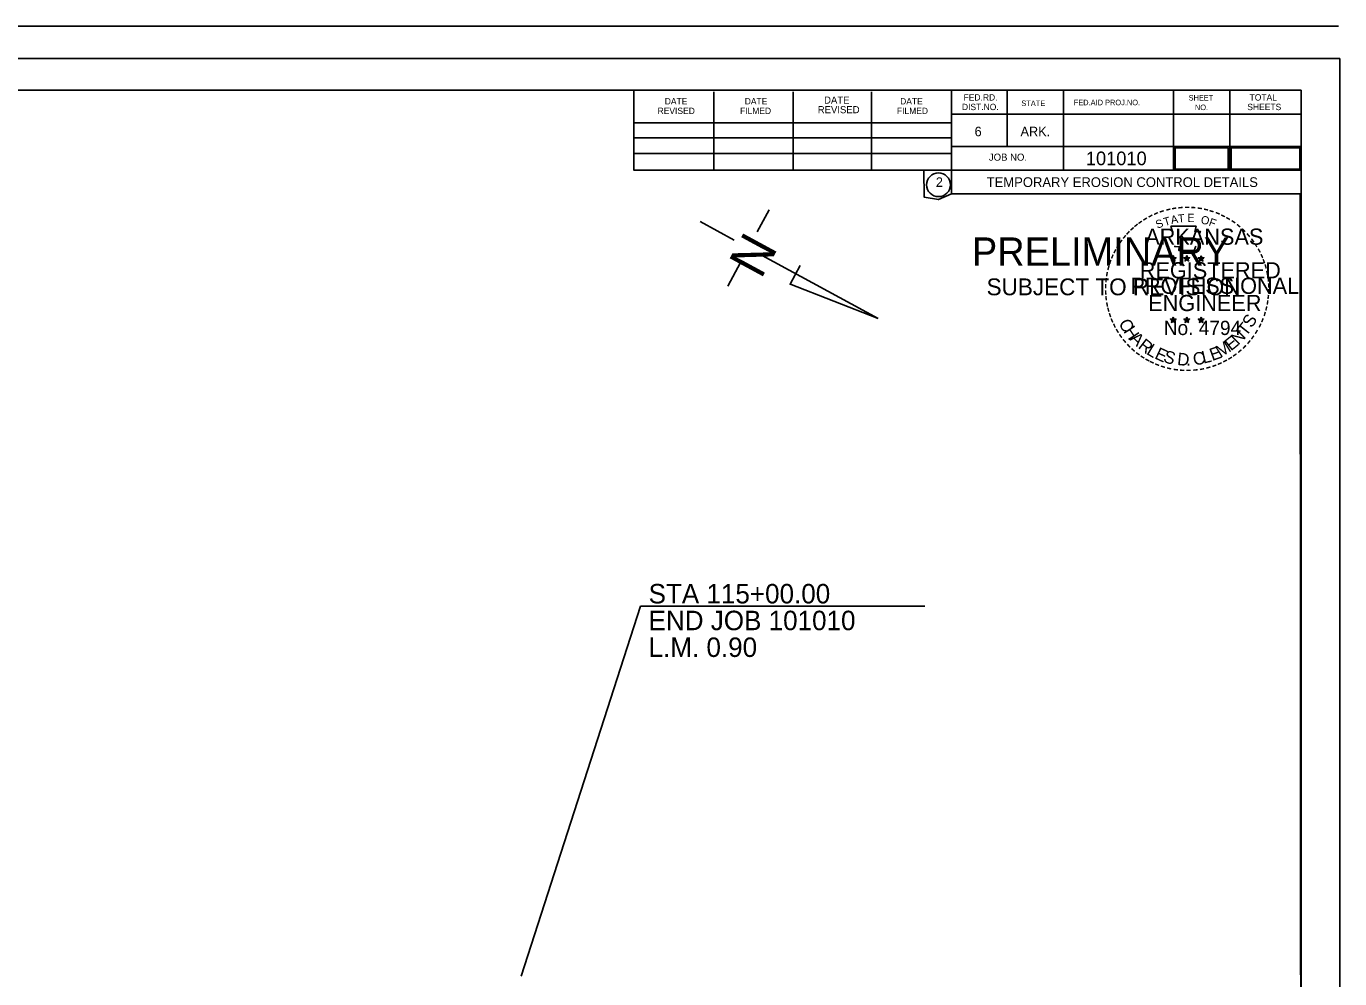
# Model space of a CAD drawing. Extents: x 7675 to 14104, y 9961 to 11168.
# Drawn here: x 10795 to 11605, y 10480 to 11067 of the extents above; entities that cross this region are included whole.
import ezdxf

# ---------------------------------------------------------------- set-up
doc = ezdxf.new("R2010")
doc.units = 0
for name, color, linetype in [('C-PSVP', 7, 'Continuous'), ('Clearing and Grubbing Ditch Checks', 7, 'Continuous'), ('Clearing and Grubbing Silt Fence', 7, 'Continuous'), ('Clearing and Grubbing Temp Seeding', 7, 'Continuous'), ('GREEN_TXT', 7, 'Continuous'), ('SEAL-INFO', 7, 'Continuous'), ('SIGNATURE', 7, 'Continuous'), ('Stage 1 Construction', 7, 'Continuous'), ('Stage 1 Ditch Checks', 7, 'Continuous')]:
    doc.layers.add(name, color=color, linetype=linetype)

msp = doc.modelspace()

# ---------------------------------------------------------------- linework, layer by layer
for p, q in [((11210.34, 10946.25), (11231.36, 10934.83)), ((11253.03, 10953.51), (11245.66, 10939.95)), ((11248.68, 10925.42), (11320.17, 10886.59)), ((11235.36, 10920.97), (11227.49, 10906.49)), ((11272.11, 10919.12), (11265.94, 10907.75)), ((11320.17, 10886.59), (11265.57, 10907.97))]:
    msp.add_line(p, q)
at = {"layer": 'C-PSVP'}
for p, q in [((11500.31, 10924.04), (11502.05, 10923.49)), ((11500.31, 10924.04), (11501.57, 10923.82)), ((11500.31, 10924.04), (11501.49, 10923.43)), ((11500.97, 10922), (11502.05, 10923.49)), ((11500.97, 10922), (11501.6, 10923.22)), ((11500.97, 10922), (11502.04, 10923.09)), ((11502.05, 10925.31), (11501.85, 10924.05)), ((11503.12, 10922), (11502.04, 10923.07)), ((11502.05, 10923.49), (11502.05, 10925.31)), ((11502.05, 10925.31), (11502.3, 10924.06)), ((11503.79, 10924.04), (11502.05, 10923.49)), ((11503.12, 10922), (11502.05, 10923.49)), ((11503.79, 10924.04), (11502.36, 10923.8)), ((11503.12, 10922), (11502.43, 10923.46)), ((11503.79, 10924.04), (11502.77, 10923.53)), ((11508.66, 10924.04), (11510.4, 10923.49)), ((11508.66, 10924.04), (11509.92, 10923.82)), ((11508.66, 10924.04), (11509.84, 10923.43)), ((11509.32, 10922), (11510.4, 10923.49)), ((11509.32, 10922), (11509.95, 10923.22)), ((11509.32, 10922), (11510.39, 10923.09)), ((11510.4, 10925.31), (11510.2, 10924.05)), ((11511.47, 10922), (11510.39, 10923.07)), ((11510.4, 10923.49), (11510.4, 10925.31)), ((11510.4, 10925.31), (11510.65, 10924.06)), ((11512.14, 10924.04), (11510.4, 10923.49)), ((11511.47, 10922), (11510.4, 10923.49)), ((11512.14, 10924.04), (11510.71, 10923.8)), ((11511.47, 10922), (11510.78, 10923.46)), ((11512.14, 10924.04), (11511.12, 10923.53)), ((11517.48, 10923.98), (11519.22, 10923.43)), ((11517.48, 10923.98), (11518.74, 10923.76)), ((11517.48, 10923.98), (11518.66, 10923.37)), ((11518.14, 10921.94), (11519.22, 10923.43)), ((11518.14, 10921.94), (11518.77, 10923.16)), ((11518.14, 10921.94), (11519.21, 10923.03)), ((11519.22, 10925.25), (11519.02, 10923.99)), ((11520.29, 10921.94), (11519.21, 10923.01)), ((11519.22, 10923.43), (11519.22, 10925.25)), ((11519.22, 10925.25), (11519.47, 10924)), ((11520.96, 10923.98), (11519.22, 10923.43)), ((11520.29, 10921.94), (11519.22, 10923.43)), ((11520.96, 10923.98), (11519.53, 10923.74)), ((11520.29, 10921.94), (11519.6, 10923.4)), ((11520.96, 10923.98), (11519.94, 10923.47)), ((11500.29, 10886.18), (11502.03, 10885.62)), ((11500.29, 10886.18), (11501.55, 10885.95)), ((11500.29, 10886.18), (11501.47, 10885.57)), ((11500.95, 10884.14), (11502.03, 10885.62)), ((11500.95, 10884.14), (11501.58, 10885.36)), ((11500.95, 10884.14), (11502.02, 10885.22)), ((11502.03, 10887.45), (11501.83, 10886.19)), ((11503.1, 10884.14), (11502.02, 10885.21)), ((11502.03, 10885.62), (11502.03, 10887.45)), ((11502.03, 10887.45), (11502.28, 10886.2)), ((11503.77, 10886.18), (11502.03, 10885.62)), ((11503.1, 10884.14), (11502.03, 10885.62)), ((11503.77, 10886.18), (11502.34, 10885.93)), ((11503.1, 10884.14), (11502.41, 10885.59)), ((11503.77, 10886.18), (11502.75, 10885.67)), ((11508.63, 10886.18), (11510.38, 10885.62)), ((11508.63, 10886.18), (11509.9, 10885.95)), ((11508.63, 10886.18), (11509.82, 10885.57)), ((11509.3, 10884.14), (11510.38, 10885.62)), ((11509.3, 10884.14), (11509.93, 10885.36)), ((11509.3, 10884.14), (11510.37, 10885.22)), ((11510.38, 10887.45), (11510.17, 10886.19)), ((11511.44, 10884.14), (11510.37, 10885.21)), ((11510.38, 10885.62), (11510.38, 10887.45)), ((11510.38, 10887.45), (11510.62, 10886.2)), ((11512.11, 10886.18), (11510.38, 10885.62)), ((11511.44, 10884.14), (11510.38, 10885.62)), ((11512.11, 10886.18), (11510.68, 10885.93)), ((11511.44, 10884.14), (11510.76, 10885.59)), ((11512.11, 10886.18), (11511.09, 10885.67)), ((11517.47, 10886.13), (11519.21, 10885.57)), ((11517.47, 10886.13), (11518.73, 10885.9)), ((11517.47, 10886.13), (11518.65, 10885.52)), ((11518.13, 10884.09), (11519.21, 10885.57)), ((11518.13, 10884.09), (11518.76, 10885.31)), ((11518.13, 10884.09), (11519.2, 10885.17)), ((11519.21, 10887.4), (11519.01, 10886.14)), ((11520.28, 10884.09), (11519.2, 10885.16)), ((11519.21, 10885.57), (11519.21, 10887.4)), ((11519.21, 10887.4), (11519.46, 10886.15)), ((11520.95, 10886.13), (11519.21, 10885.57)), ((11520.28, 10884.09), (11519.21, 10885.57)), ((11520.95, 10886.13), (11519.52, 10885.88)), ((11520.28, 10884.09), (11519.59, 10885.54)), ((11520.95, 10886.13), (11519.93, 10885.62))]:
    msp.add_line(p, q, dxfattribs=at)
for points in [[(11500.51, 10943.43), (11501.86, 10939.3)], [(11518.07, 10938.82), (11518.78, 10940.24), (11515.35, 10940.12), (11516.09, 10943.43), (11500.51, 10943.43)], [(11502.97, 10931.32), (11502.97, 10930.88), (11505.79, 10930.79), (11505.52, 10928.42), (11514.87, 10928.42), (11515.87, 10931.1)], [(11502.05, 10925.31), (11503.12, 10922), (11500.31, 10924.04), (11503.79, 10924.04), (11500.97, 10922), (11502.05, 10925.31)], [(11510.4, 10925.31), (11511.47, 10922), (11508.66, 10924.04), (11512.14, 10924.04), (11509.32, 10922), (11510.4, 10925.31)], [(11519.22, 10925.25), (11520.29, 10921.94), (11517.48, 10923.98), (11520.96, 10923.98), (11518.14, 10921.94), (11519.22, 10925.25)], [(11502.03, 10887.45), (11503.1, 10884.14), (11500.29, 10886.18), (11503.77, 10886.18), (11500.95, 10884.14), (11502.03, 10887.45)], [(11510.38, 10887.45), (11511.44, 10884.14), (11508.63, 10886.18), (11512.11, 10886.18), (11509.3, 10884.14), (11510.38, 10887.45)], [(11519.21, 10887.4), (11520.28, 10884.09), (11517.47, 10886.13), (11520.95, 10886.13), (11518.13, 10884.09), (11519.21, 10887.4)]]:
    msp.add_lwpolyline(points, dxfattribs=at)
for centre, radius in [((11502.05, 10923.48), 0.861), ((11502.05, 10923.48), 0.723), ((11502.05, 10923.48), 0.579), ((11502.05, 10923.48), 0.495), ((11502.05, 10923.48), 0.374), ((11502.05, 10923.48), 0.248), ((11502.05, 10923.48), 0.148), ((11510.4, 10923.48), 0.861), ((11510.4, 10923.48), 0.723), ((11510.4, 10923.48), 0.579), ((11510.4, 10923.48), 0.495), ((11510.4, 10923.48), 0.374), ((11510.4, 10923.48), 0.248), ((11510.4, 10923.48), 0.148), ((11519.22, 10923.42), 0.861), ((11519.22, 10923.42), 0.723), ((11519.22, 10923.42), 0.579), ((11519.22, 10923.42), 0.495), ((11519.22, 10923.42), 0.374), ((11519.22, 10923.42), 0.248), ((11519.22, 10923.42), 0.148), ((11502.03, 10885.62), 0.861), ((11502.03, 10885.62), 0.723), ((11502.03, 10885.62), 0.579), ((11502.03, 10885.62), 0.495), ((11502.03, 10885.62), 0.374), ((11502.03, 10885.62), 0.248), ((11502.03, 10885.62), 0.148), ((11510.37, 10885.62), 0.861), ((11510.37, 10885.62), 0.723), ((11510.37, 10885.62), 0.579), ((11510.37, 10885.62), 0.495), ((11510.37, 10885.62), 0.374), ((11510.37, 10885.62), 0.248), ((11510.37, 10885.62), 0.148), ((11519.21, 10885.57), 0.861), ((11519.21, 10885.57), 0.723), ((11519.21, 10885.57), 0.579), ((11519.21, 10885.57), 0.495), ((11519.21, 10885.57), 0.374), ((11519.21, 10885.57), 0.248), ((11519.21, 10885.57), 0.148)]:
    msp.add_circle(centre, radius, dxfattribs=at)
at = {"layer": 'Clearing and Grubbing Ditch Checks'}
msp.add_lwpolyline([(11503.22, 10978.65), (11535.88, 10978.65), (11535.88, 10991.85), (11503.22, 10991.85)], close=True, dxfattribs=at)
at = {"layer": 'Clearing and Grubbing Silt Fence'}
msp.add_lwpolyline([(11537.72, 10978.65), (11580.08, 10978.65), (11580.08, 10991.85), (11537.72, 10991.85)], close=True, dxfattribs=at)
at = {"layer": 'GREEN_TXT'}
for p, q in [((11603.9, 11066.7), (9843.9, 11066.7)), ((10000, 11027.3), (11580.9, 11027.3)), ((11169.6, 10977.9), (11169.6, 11027.3)), ((11365.4, 11027.3), (11365.4, 10963.3)), ((11399.6, 11027.3), (11399.6, 10992.6)), ((11434.3, 11027.3), (11434.3, 10977.9)), ((11502.2, 11027.3), (11502.2, 10977.9)), ((11536.9, 11027.3), (11536.9, 10977.9)), ((11580.9, 10000), (11580.9, 11027.3)), ((11218.9, 10977.9), (11218.9, 11026.3)), ((11267.7, 10977.9), (11267.7, 11026.3)), ((11316.1, 10977.9), (11316.1, 11026.3)), ((11580.9, 11012.6), (11365.4, 11012.6)), ((11580.9, 11012.7), (11580.9, 11012.7)), ((11169.6, 11007.2), (11365.4, 11007.2)), ((11169.6, 10997.9), (11365.4, 10997.9)), ((11169.6, 10988.2), (11365.4, 10988.2)), ((11580.9, 10992.6), (11365.4, 10992.6)), ((11580.9, 10977.9), (11169.6, 10977.9)), ((11365.4, 10963.3), (11580.9, 10963.3))]:
    msp.add_line(p, q, dxfattribs=at)
msp.add_circle((11357.33, 10968.98), 7.33, dxfattribs=at)
at = {"layer": 'SEAL-INFO'}
msp.add_lwpolyline([(9937.96, 11046.77), (11604.66, 11046.77), (11604.66, 9980.09), (9937.96, 9980.09)], close=True, dxfattribs=at)
at = {"layer": 'Stage 1 Construction'}
msp.add_lwpolyline([(11348.91, 10709.13), (11173.68, 10709.13), (11100, 10480.99)], dxfattribs=at)
at = {"layer": 'Stage 1 Ditch Checks'}
msp.add_lwpolyline([(10000, 10000), (11580.9, 10000), (11580.3, 10963.3), (11365.4, 10963.3), (11357.31, 10959.87), (11348.49, 10961.4), (11348.26, 10977.9), (11169.6, 10977.9), (11169.6, 11027.3), (10000, 11027.3)], close=True, dxfattribs=at)

# ---------------------------------------------------------------- texts
msp.add_text('N', height=23.27, rotation=241.48958).set_placement((11238.17, 10941.17))
at = {"layer": 'C-PSVP'}
for s, height, rotation, p in [('-', 8, 13.63015, (11498, 10950.27)), ('-', 8, 10.21935, (11501.39, 10951.08)), ('-', 8, 5.89682, (11505.04, 10951.63)), ('-', 8, 0.18623, (11508.9, 10951.99)), ('-', 8, 357.74304, (11512.51, 10951.93)), ('-', 8, 352.16172, (11516.23, 10951.65)), ('-', 8, 347.20489, (11519.83, 10951.08)), ('-', 8, 36.23174, (11482.04, 10942.31)), ('-', 8, 34.06357, (11484.93, 10944.29)), ('-', 8, 28.79182, (11487.92, 10946.14)), ('-', 8, 24.30721, (11491.08, 10947.72)), ('S', 5, 21.59401, (11492.29, 10941.82)), ('-', 8, 19.17608, (11494.25, 10949.07)), ('T', 5, 16.4036, (11496.86, 10943.48)), ('A', 5, 11.21318, (11500.99, 10944.73)), ('T', 5, 6.02276, (11505.23, 10945.56)), ('E', 5, 0.83234, (11510.76, 10946.11)), ('O', 5, 350.4515, (11518.78, 10945.06)), ('F', 5, 340.07066, (11523.55, 10943.92)), ('-', 8, 342.3362, (11523, 10950.3)), ('-', 8, 337.85509, (11526.68, 10949.19)), ('-', 8, 334.12109, (11529.83, 10947.83)), ('-', 8, 329.64089, (11532.73, 10946.42)), ('-', 8, 325.86266, (11535.94, 10944.61)), ('-', 8, 50.61417, (11473.24, 10933.52)), ('-', 8, 48.42305, (11475.26, 10935.95)), ('-', 8, 42.96224, (11477.5, 10938.34)), ('-', 8, 38.95066, (11479.66, 10940.42)), ('-', 8, 320.52971, (11538.99, 10942.48)), ('-', 8, 315.57859, (11541.99, 10940.04)), ('-', 8, 309.87973, (11544.83, 10937.29)), ('-', 8, 58.07063, (11469.55, 10928.05)), ('-', 8, 54.23247, (11471.18, 10930.68)), ('-', 8, 306.65218, (11547.46, 10934.28)), ('-', 7, 303.67529, (11549.89, 10931.44)), ('-', 8, 72.39447, (11465.6, 10918.77)), ('-', 8, 67.77427, (11466.69, 10921.92)), ('-', 8, 62.87135, (11467.99, 10924.98)), ('-', 8, 299.66835, (11551.48, 10928.41)), ('-', 8, 294.66279, (11553.1, 10925.35)), ('-', 8, 290.57283, (11554.39, 10922.46)), ('-', 8, 81.20126, (11463.95, 10911.64)), ('-', 8, 75.46096, (11464.61, 10915.2)), ('-', 8, 285.12326, (11555.56, 10919.56)), ('-', 8, 280.54934, (11556.56, 10915.85)), ('-', 8, 89.06224, (11463.45, 10904.68)), ('-', 8, 85.18634, (11463.57, 10908.18)), ('-', 8, 276.59616, (11557.37, 10912.01)), ('-', 8, 274.33011, (11557.67, 10908.4)), ('-', 8, 94.19588, (11463.62, 10901.05)), ('-', 8, 98.94793, (11463.98, 10897.72)), ('-', 8, 260.99529, (11557.39, 10898.64)), ('-', 8, 263.5172, (11557.74, 10901.91)), ('-', 8, 269.94067, (11557.84, 10905.24)), ('-', 8, 101.71495, (11464.66, 10894.05)), ('-', 8, 105.45785, (11465.47, 10891.08)), ('-', 8, 109.08742, (11466.54, 10887.92)), ('-', 8, 255.7626, (11555.88, 10891.81)), ('-', 8, 255.7626, (11556.84, 10895.25)), ('-', 8, 114.06432, (11467.81, 10884.94)), ('-', 8, 115.72885, (11469.34, 10881.85)), ('C', 7.7, 296.9133, (11468.18, 10883.9)), ('H', 7.7, 303.27986, (11471.13, 10878.7)), ('T', 7.7, 51.51144, (11546.85, 10875.07)), ('S', 7.7, 57.878, (11550.49, 10880.28)), ('-', 8, 244.61971, (11553.51, 10885.14)), ('-', 8, 247.88866, (11554.82, 10888.29)), ('-', 8, 120.44712, (11471.12, 10878.92)), ('-', 8, 125.89344, (11473.14, 10876.12)), ('-', 8, 130.71812, (11475.45, 10873.36)), ('A', 7.7, 316.01299, (11474.77, 10873.57)), ('R', 7.7, 322.37955, (11479.9, 10868.66)), ('E', 7.7, 38.77831, (11537.6, 10866.21)), ('N', 7.7, 45.14487, (11542.05, 10869.86)), ('-', 8, 231.25377, (11547.38, 10875.29)), ('-', 8, 233.84524, (11549.53, 10878.12)), ('-', 8, 239.07125, (11551.54, 10881.38)), ('-', 8, 134.22381, (11478.03, 10870.63)), ('-', 8, 138.93382, (11480.66, 10868.31)), ('-', 8, 144.64634, (11483.44, 10866.28)), ('L', 7.7, 328.74612, (11485.03, 10864.91)), ('E', 7.7, 335.11268, (11490.06, 10862.12)), ('S', 7.7, 341.47924, (11495.39, 10859.96)), ('D', 7.7, 354.21237, (11504.22, 10857.9)), ('C', 7.7, 6.94549, (11514.65, 10857.71)), ('L', 7.7, 13.31206, (11520.57, 10858.66)), ('E', 7.7, 19.67862, (11526.09, 10860.26)), ('M', 7.7, 32.41175, (11531.2, 10862.15)), ('-', 8, 215.73633, (11539.63, 10867.56)), ('-', 8, 221.08509, (11542.37, 10869.92)), ('-', 8, 225.76533, (11544.98, 10872.47)), ('-', 8, 148.08978, (11486.24, 10864.43)), ('-', 8, 151.57039, (11489.14, 10862.8)), ('-', 8, 154.60019, (11491.75, 10861.57)), ('-', 8, 158.56121, (11494.87, 10860.3)), ('-', 8, 162.79826, (11498.3, 10859.23)), ('.', 7.7, 0.57893, (11510.09, 10857.52)), ('-', 8, 195.47429, (11524.57, 10859.73)), ('-', 8, 200.71842, (11527.95, 10860.94)), ('-', 8, 204.25161, (11531.05, 10862.3)), ('-', 8, 207.35684, (11534.17, 10863.9)), ('-', 8, 212.24909, (11536.96, 10865.63)), ('-', 8, 167.55551, (11501.88, 10858.41)), ('-', 8, 173.11546, (11505.74, 10857.86)), ('-', 8, 176.51827, (11509.48, 10857.6)), ('-', 8, 181.59176, (11513.2, 10857.69)), ('-', 8, 185.81666, (11517.24, 10858.07)), ('-', 8, 191.28576, (11520.92, 10858.73))]:
    msp.add_text(s, height=height, rotation=rotation, dxfattribs=at).set_placement(p)
for s, height, p in [('ARKANSAS', 10, (11484.78, 10931.99)), ('REGISTERED', 10, (11481.39, 10911.25)), ('PROFESSIONAL', 10, (11475.65, 10901.73)), ('ENGINEER', 10, (11486.58, 10891.1)), ('No. 4794', 8.785, (11496.21, 10876.35))]:
    msp.add_text(s, height=height, dxfattribs=at).set_placement(p)
at = {"layer": 'Clearing and Grubbing Temp Seeding'}
for s, height, p in [('101010', 8.4, (11448.18, 10981.05)), ('TEMPORARY EROSION CONTROL DETAILS', 6, (11387.05, 10967.6))]:
    msp.add_text(s, height=height, dxfattribs=at).set_placement(p)
at = {"layer": 'GREEN_TXT'}
for s, height, p in [('DATE', 3.91, (11188.6, 11018.5)), ('DATE', 3.91, (11237.9, 11018.5)), ('DATE', 4.396, (11286.8, 11019)), ('DATE', 3.91, (11333.7, 11018.5)), ('DIST.NO.', 3.91, (11371.8, 11015)), ('FED.RD.', 3.91, (11372.8, 11020.9)), ('STATE', 3.42, (11408.4, 11017.5)), ('FED.AID PROJ.NO.', 3.42, (11440.7, 11018)), ('SHEET', 3.42, (11511.5, 11020.9)), ('SHEETS', 3.91, (11547.7, 11015)), ('TOTAL', 3.91, (11549.1, 11020.9)), ('REVISED', 3.91, (11184.2, 11012.59)), ('FILMED', 3.91, (11235, 11012.59)), ('REVISED', 4.396, (11282.9, 11013.09)), ('FILMED', 3.91, (11331.7, 11012.59)), ('NO.', 3.42, (11515.4, 11015)), ('6', 5.86, (11379.6, 10998.9)), ('ARK.', 5.861, (11407.9, 10998.9)), ('JOB NO.', 4.396, (11388.4, 10983.8)), ('2', 5.86, (11355.7, 10967.69))]:
    msp.add_text(s, height=height, dxfattribs=at).set_placement(p)
at = {"layer": 'SIGNATURE'}
for s, height, p in [('PRELIMINARY', 17.5, (11377.93, 10919.01)), ('SUBJECT TO REVISION', 10.3756, (11386.98, 10900.86))]:
    msp.add_text(s, height=height, dxfattribs=at).set_placement(p)
at = {"layer": 'Stage 1 Construction'}
for s, p in [('STA 115+00.00', (11178.64, 10710.88)), ('END JOB 101010', (11178.64, 10694.38)), ('L.M. 0.90', (11178.64, 10677.88))]:
    msp.add_text(s, height=12, dxfattribs=at).set_placement(p)

doc.saveas('drawing.dxf')
